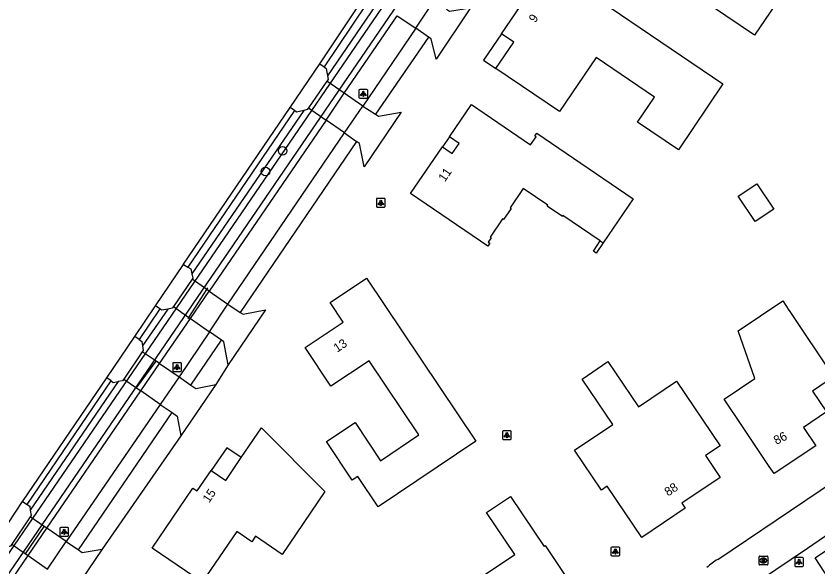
# Model space of a CAD drawing. Extents: x 158797 to 159887, y 384318 to 385255.
# Drawn here: x 158945.2 to 159036.2, y 384830.9 to 384893.5 of the extents above; entities that cross this region are included whole.
import ezdxf

# ---------------------------------------------------------------- set-up
doc = ezdxf.new("R2010")
doc.units = 0
for name, color, linetype in [('IMGEO_Berm_groen', 7, 'Continuous'), ('IMGEO_Boom', 7, 'Continuous'), ('IMGEO_Duiker', 7, 'Continuous'), ('IMGEO_Greppel_droge_sloot', 7, 'Continuous'), ('IMGEO_Groenvoorziening', 7, 'Continuous'), ('IMGEO_Lichtpunt', 7, 'Continuous'), ('IMGEO_Muur', 7, 'Continuous'), ('IMGEO_Pand', 7, 'Continuous'), ('IMGEO_Pand_nummerreeks', 7, 'Continuous'), ('IMGEO_Pand_overbouw', 7, 'Continuous'), ('IMGEO_Rijbaan_lokaal_gesloten', 7, 'Continuous'), ('IMGEO_Rijbaan_lokaal_halfverhard', 7, 'Continuous'), ('IMGEO_Rijbaan_lokaal_open', 7, 'Continuous'), ('IMGEO_Rioolput', 7, 'Continuous'), ('IMGEO_Voetpad_gesloten', 7, 'Continuous'), ('IMGEO_Voetpad_open', 7, 'Continuous')]:
    doc.layers.add(name, color=color, linetype=linetype)

msp = doc.modelspace()

# ---------------------------------------------------------------- linework, layer by layer
at = {"layer": 'IMGEO_Berm_groen'}
for points in [[(158962.43, 384860.223), (158959.562, 384856.029)], [(158956.795, 384851.982), (158946.829, 384837.41)]]:
    msp.add_lwpolyline(points, dxfattribs=at)
at = {"layer": 'IMGEO_Boom'}
for centre in [(158975.46, 384878.168), (158973.5, 384875.847)]:
    msp.add_circle(centre, 0.489, dxfattribs=at)
at = {"layer": 'IMGEO_Duiker'}
for points in [[(158964.726, 384859.119), (158964.826, 384859.275), (158966.867, 384862.445), (158966.983, 384862.625)], [(158958.884, 384851.261), (158961.107, 384854.291)], [(158946.282, 384832.45), (158948.412, 384835.535)]]:
    msp.add_lwpolyline(points, dxfattribs=at)
at = {"layer": 'IMGEO_Greppel_droge_sloot'}
for points in [[(159000.581, 384914.767), (158933.082, 384816.06)], [(158860.704, 384704.496), (158865.586, 384712.552), (158874.82, 384728.136), (158879.769, 384735.7), (158885.859, 384744.611), (158889.814, 384750.397), (158895.665, 384758.96), (158904.883, 384772.441), (158934.173, 384815.304), (158999.419, 384910.783)]]:
    msp.add_lwpolyline(points, dxfattribs=at)
at = {"layer": 'IMGEO_Groenvoorziening'}
for points in [[(158985.982, 384894.666), (158980.534, 384886.698)], [(158982.459, 384884.718), (158988.462, 384893.502)], [(158977.846, 384882.767), (158965.16, 384864.217)], [(158980.382, 384881.678), (158967.118, 384862.269)], [(158961.487, 384854.03), (158964.992, 384859.158)], [(158969.286, 384853.901), (158967.876, 384851.67)], [(158948.709, 384835.331), (158959.366, 384850.926)], [(158963.909, 384845.829), (158954.984, 384832.978)], [(158933.128, 384812.532), (158946.591, 384832.233)]]:
    msp.add_lwpolyline(points, dxfattribs=at)
at = {"layer": 'IMGEO_Lichtpunt'}
for p, q in [((158984.119, 384885.053), (158984.119, 384884.246)), ((158984.119, 384885.053), (158984.119, 384884.246)), ((158985.021, 384885.148), (158984.213, 384885.148)), ((158985.021, 384885.148), (158984.213, 384885.148)), ((158985.115, 384884.246), (158985.115, 384885.053)), ((158985.115, 384884.246), (158985.115, 384885.053)), ((158984.213, 384884.152), (158985.021, 384884.152)), ((158984.213, 384884.152), (158985.021, 384884.152)), ((158986.101, 384872.684), (158986.101, 384871.877)), ((158986.101, 384872.684), (158986.101, 384871.877)), ((158987.003, 384872.779), (158986.195, 384872.779)), ((158987.003, 384872.779), (158986.195, 384872.779)), ((158987.097, 384871.877), (158987.097, 384872.684)), ((158987.097, 384871.877), (158987.097, 384872.684)), ((158986.195, 384871.783), (158987.003, 384871.783)), ((158986.195, 384871.783), (158987.003, 384871.783)), ((158962.982, 384854.039), (158962.982, 384853.232)), ((158962.982, 384854.039), (158962.982, 384853.232)), ((158963.884, 384854.134), (158963.076, 384854.134)), ((158963.884, 384854.134), (158963.076, 384854.134)), ((158963.978, 384853.232), (158963.978, 384854.039)), ((158963.978, 384853.232), (158963.978, 384854.039)), ((158963.076, 384853.138), (158963.884, 384853.138)), ((158963.076, 384853.138), (158963.884, 384853.138)), ((159000.403, 384846.31), (159000.403, 384845.503)), ((159000.403, 384846.31), (159000.403, 384845.503)), ((159001.305, 384846.405), (159000.497, 384846.405)), ((159001.305, 384846.405), (159000.497, 384846.405)), ((159001.399, 384845.503), (159001.399, 384846.31)), ((159001.399, 384845.503), (159001.399, 384846.31)), ((159000.497, 384845.409), (159001.305, 384845.409)), ((159000.497, 384845.409), (159001.305, 384845.409)), ((158950.181, 384835.336), (158950.181, 384834.529)), ((158950.181, 384835.336), (158950.181, 384834.529)), ((158951.083, 384835.431), (158950.275, 384835.431)), ((158951.083, 384835.431), (158950.275, 384835.431)), ((158951.177, 384834.529), (158951.177, 384835.336)), ((158951.177, 384834.529), (158951.177, 384835.336)), ((158950.275, 384834.435), (158951.083, 384834.435)), ((158950.275, 384834.435), (158951.083, 384834.435)), ((159012.717, 384833.106), (159012.717, 384832.299)), ((159012.717, 384833.106), (159012.717, 384832.299)), ((159013.619, 384833.201), (159012.811, 384833.201)), ((159013.619, 384833.201), (159012.811, 384833.201)), ((159013.713, 384832.299), (159013.713, 384833.106)), ((159013.713, 384832.299), (159013.713, 384833.106)), ((159012.811, 384832.205), (159013.619, 384832.205)), ((159012.811, 384832.205), (159013.619, 384832.205)), ((159033.559, 384831.915), (159033.559, 384831.108)), ((159033.559, 384831.915), (159033.559, 384831.108)), ((159034.461, 384832.01), (159033.653, 384832.01)), ((159034.461, 384832.01), (159033.653, 384832.01)), ((159034.555, 384831.108), (159034.555, 384831.915)), ((159034.555, 384831.108), (159034.555, 384831.915)), ((159033.653, 384831.014), (159034.461, 384831.014)), ((159033.653, 384831.014), (159034.461, 384831.014))]:
    msp.add_line(p, q, dxfattribs=at)
for points in [[(158984.493, 384884.717), (158984.532, 384884.689), (158984.344, 384884.427), (158984.306, 384884.454), (158984.493, 384884.717)], [(158984.595, 384884.669), (158984.642, 384884.669), (158984.642, 384884.347), (158984.595, 384884.347), (158984.595, 384884.669)], [(158984.705, 384884.689), (158984.743, 384884.716), (158984.93, 384884.454), (158984.891, 384884.426), (158984.705, 384884.689)], [(158986.475, 384872.348), (158986.514, 384872.32), (158986.326, 384872.058), (158986.288, 384872.085), (158986.475, 384872.348)], [(158986.577, 384872.3), (158986.624, 384872.3), (158986.624, 384871.978), (158986.577, 384871.978), (158986.577, 384872.3)], [(158986.687, 384872.32), (158986.725, 384872.347), (158986.912, 384872.085), (158986.873, 384872.057), (158986.687, 384872.32)], [(158963.356, 384853.703), (158963.395, 384853.675), (158963.207, 384853.413), (158963.169, 384853.44), (158963.356, 384853.703)], [(158963.458, 384853.655), (158963.505, 384853.655), (158963.505, 384853.333), (158963.458, 384853.333), (158963.458, 384853.655)], [(158963.568, 384853.675), (158963.606, 384853.702), (158963.793, 384853.44), (158963.754, 384853.412), (158963.568, 384853.675)], [(159000.777, 384845.974), (159000.816, 384845.946), (159000.628, 384845.684), (159000.59, 384845.711), (159000.777, 384845.974)], [(159000.879, 384845.926), (159000.926, 384845.926), (159000.926, 384845.604), (159000.879, 384845.604), (159000.879, 384845.926)], [(159000.989, 384845.946), (159001.027, 384845.973), (159001.214, 384845.711), (159001.175, 384845.683), (159000.989, 384845.946)], [(158950.555, 384835), (158950.594, 384834.972), (158950.406, 384834.71), (158950.368, 384834.737), (158950.555, 384835)], [(158950.657, 384834.952), (158950.704, 384834.952), (158950.704, 384834.63), (158950.657, 384834.63), (158950.657, 384834.952)], [(158950.767, 384834.972), (158950.805, 384834.999), (158950.992, 384834.737), (158950.953, 384834.709), (158950.767, 384834.972)], [(159013.091, 384832.77), (159013.13, 384832.742), (159012.942, 384832.48), (159012.904, 384832.507), (159013.091, 384832.77)], [(159013.193, 384832.722), (159013.24, 384832.722), (159013.24, 384832.4), (159013.193, 384832.4), (159013.193, 384832.722)], [(159013.303, 384832.742), (159013.341, 384832.769), (159013.528, 384832.507), (159013.489, 384832.479), (159013.303, 384832.742)], [(159033.933, 384831.579), (159033.972, 384831.551), (159033.784, 384831.289), (159033.746, 384831.316), (159033.933, 384831.579)], [(159034.035, 384831.531), (159034.082, 384831.531), (159034.082, 384831.209), (159034.035, 384831.209), (159034.035, 384831.531)], [(159034.145, 384831.551), (159034.183, 384831.578), (159034.37, 384831.316), (159034.331, 384831.288), (159034.145, 384831.551)]]:
    msp.add_lwpolyline(points, dxfattribs=at)
for centre in [(158984.618, 384884.851), (158986.6, 384872.482), (158963.481, 384853.837), (159000.902, 384846.108), (158950.68, 384835.134), (159013.216, 384832.904), (159034.058, 384831.713)]:
    msp.add_circle(centre, 0.0994, dxfattribs=at)
for centre, start, end in [((158984.213, 384885.053), 90, 180), ((158984.213, 384885.053), 90, 180), ((158985.021, 384885.053), 0, 90), ((158985.021, 384885.053), 0, 90), ((158984.213, 384884.246), 180, 270), ((158984.213, 384884.246), 180, 270), ((158985.021, 384884.246), 270, 0), ((158985.021, 384884.246), 270, 360), ((158986.195, 384872.684), 90, 180), ((158986.195, 384872.684), 90, 180), ((158987.003, 384872.684), 0, 90), ((158987.003, 384872.684), 0, 90), ((158986.195, 384871.877), 180, 270), ((158986.195, 384871.877), 180, 270), ((158987.003, 384871.877), 270, 0), ((158987.003, 384871.877), 270, 360), ((158963.076, 384854.039), 90, 180), ((158963.076, 384854.039), 90, 180), ((158963.884, 384854.039), 0, 90), ((158963.884, 384854.039), 0, 90), ((158963.076, 384853.232), 180, 270), ((158963.076, 384853.232), 180, 270), ((158963.884, 384853.232), 270, 0), ((158963.884, 384853.232), 270, 360), ((159000.497, 384846.31), 90, 180), ((159000.497, 384846.31), 90, 180), ((159001.305, 384846.31), 0, 90), ((159001.305, 384846.31), 0, 90), ((159000.497, 384845.503), 180, 270), ((159000.497, 384845.503), 180, 270), ((159001.305, 384845.503), 270, 0), ((159001.305, 384845.503), 270, 360), ((158950.275, 384835.336), 90, 180), ((158950.275, 384835.336), 90, 180), ((158951.083, 384835.336), 0, 90), ((158951.083, 384835.336), 0, 90), ((158950.275, 384834.529), 180, 270), ((158950.275, 384834.529), 180, 270), ((158951.083, 384834.529), 270, 0), ((158951.083, 384834.529), 270, 360), ((159012.811, 384833.106), 90, 180), ((159012.811, 384833.106), 90, 180), ((159013.619, 384833.106), 0, 90), ((159013.619, 384833.106), 0, 90), ((159012.811, 384832.299), 180, 270), ((159012.811, 384832.299), 180, 270), ((159013.619, 384832.299), 270, 0), ((159013.619, 384832.299), 270, 360), ((159033.653, 384831.915), 90, 180), ((159033.653, 384831.915), 90, 180), ((159034.461, 384831.915), 0, 90), ((159034.461, 384831.915), 0, 90), ((159033.653, 384831.108), 180, 270), ((159033.653, 384831.108), 180, 270), ((159034.461, 384831.108), 270, 0), ((159034.461, 384831.108), 270, 360)]:
    msp.add_arc(centre, 0.0946, start, end, dxfattribs=at)
at = {"layer": 'IMGEO_Muur'}
msp.add_lwpolyline([(159011.829, 384867.738), (159011.04, 384866.573), (159010.716, 384866.797), (159011.506, 384867.958)], dxfattribs=at)
at = {"layer": 'IMGEO_Pand'}
for points in [[(159015.875, 384900.192), (159018.834, 384904.498), (159019.364, 384905.269), (159019.421, 384905.352), (159021.623, 384908.555), (159021.682, 384908.641), (159021.694, 384908.658), (159034.76, 384899.792), (159028.998, 384891.291), (159015.875, 384900.192)], [(159011.04, 384888.774), (159006.868, 384882.635), (158999.666, 384887.522), (159001.7, 384890.513), (159000.294, 384891.469), (159005.589, 384899.258), (159025.424, 384885.771), (159020.365, 384878.305), (159015.728, 384881.447), (159017.653, 384884.287), (159011.04, 384888.774)], [(159011.506, 384867.958), (159007.264, 384870.84), (159007.196, 384870.739), (159005.478, 384871.913), (159005.546, 384872.012), (159002.764, 384873.909), (159001.27, 384871.702), (159001.372, 384871.631), (159000.518, 384870.374), (159000.414, 384870.445), (158999.02, 384868.387), (158999.119, 384868.319), (158998.781, 384867.822), (158998.962, 384867.697), (158998.741, 384867.376), (158989.978, 384873.324), (158993.603, 384878.635), (158994.71, 384877.879), (158995.481, 384879.008), (158994.374, 384879.764), (158996.871, 384883.423), (159003.602, 384878.851), (159004.228, 384879.771), (159004.079, 384879.872), (159004.298, 384880.195), (159015.218, 384872.74), (159011.829, 384867.738)], [(159027.164, 384873.025), (159029.262, 384874.429), (159031.177, 384871.568), (159029.08, 384870.164), (159027.164, 384873.025)], [(159011.506, 384867.958), (159011.829, 384867.738)], [(158986.293, 384837.782), (158983.977, 384841.225), (158983.342, 384840.798), (158980.426, 384845.178), (158983.673, 384847.339), (158986.553, 384843.009), (158990.899, 384845.935), (158985.261, 384854.357), (158980.931, 384851.468), (158978.016, 384855.838), (158982.332, 384858.725), (158980.863, 384860.973), (158984.967, 384863.713), (158997.375, 384845.232), (158986.293, 384837.782)], [(159025.553, 384850), (159029.032, 384852.333), (159027.162, 384857.757), (159032.196, 384861.138), (159032.903, 384860.082), (159032.92, 384860.056), (159037.982, 384852.519), (159035.574, 384850.902), (159037.16, 384848.541), (159034.555, 384846.792), (159035.95, 384844.712), (159031.225, 384841.543), (159030.677, 384842.359), (159027.494, 384847.106), (159025.553, 384850)], [(159012.274, 384840.105), (159011.634, 384839.672), (159008.574, 384844.194), (159012.914, 384847.131), (159009.429, 384852.279), (159012.353, 384854.258), (159015.834, 384849.113), (159020.163, 384852.043), (159025.111, 384844.69), (159023.449, 384843.588), (159025.118, 384841.102), (159020.761, 384838.175), (159021.123, 384837.636), (159016.198, 384834.308), (159012.274, 384840.105)], [(158975.414, 384832.374), (158972.397, 384834.428), (158971.973, 384833.806), (158970.251, 384834.978), (158966.332, 384829.22), (158960.645, 384833.09), (158965.284, 384839.907), (158965.772, 384839.575), (158967.348, 384841.89), (158968.995, 384840.769), (158970.764, 384843.357), (158973.066, 384846.723), (158980.262, 384839.497), (158975.414, 384832.374)], [(158998.352, 384830.067), (159001.8, 384832.363), (158998.598, 384837.128), (159001.316, 384838.955), (159005.13, 384833.279), (159005.266, 384833.371), (159007.67, 384829.769), (159007.516, 384829.666), (159013.04, 384821.413), (159013.085, 384821.346), (159010.36, 384819.522), (159010.989, 384818.583), (159010.876, 384818.508), (159011.37, 384817.771), (159006.845, 384814.748), (159005.112, 384817.324), (159005.278, 384817.436), (159003.088, 384820.674), (159004.176, 384821.398), (158998.352, 384830.067)]]:
    msp.add_lwpolyline(points, dxfattribs=at)
at = {"layer": 'IMGEO_Pand_overbouw'}
for points in [[(159000.294, 384891.469), (158998.26, 384888.476), (158999.666, 384887.522), (159001.7, 384890.513)], [(158994.374, 384879.764), (158993.603, 384878.635), (158994.71, 384877.879), (158995.481, 384879.008)], [(158967.348, 384841.89), (158968.995, 384840.769), (158970.764, 384843.357), (158969.112, 384844.481)]]:
    msp.add_lwpolyline(points, close=True, dxfattribs=at)
at = {"layer": 'IMGEO_Rijbaan_lokaal_gesloten'}
for points in [[(158979.681, 384888.06), (158979.682, 384888.062), (158984.463, 384895.206)], [(158990.581, 384892.084), (158992.62, 384895.18)], [(158988.462, 384893.502), (158990.581, 384892.084)], [(158976.299, 384883.094), (158979.681, 384888.06)], [(158978.393, 384883.063), (158980.382, 384881.678), (158982.459, 384884.718), (158980.472, 384886.086), (158978.393, 384883.063)], [(158980.382, 384881.678), (158982.459, 384884.718)], [(158984.577, 384883.259), (158982.459, 384884.718)], [(158964.203, 384865.296), (158964.218, 384865.318), (158976.299, 384883.094)], [(158982.48, 384880.216), (158984.577, 384883.259)], [(158982.48, 384880.216), (158980.382, 384881.678)], [(158961.017, 384860.587), (158964.203, 384865.296)], [(158967.118, 384862.269), (158966.867, 384862.445), (158965.192, 384863.623), (158963.065, 384860.518), (158964.826, 384859.275), (158964.992, 384859.158), (158967.118, 384862.269)], [(158964.992, 384859.158), (158967.118, 384862.269)], [(158967.118, 384862.269), (158969.244, 384860.774)], [(158967.161, 384857.628), (158969.244, 384860.774)], [(158958.685, 384857.123), (158961.017, 384860.587)], [(158964.992, 384859.158), (158967.161, 384857.628)], [(158955.504, 384852.399), (158958.685, 384857.123)], [(158961.487, 384854.03), (158961.107, 384854.291), (158959.531, 384855.374), (158957.432, 384852.267), (158958.884, 384851.261), (158959.366, 384850.926), (158961.487, 384854.03)], [(158959.366, 384850.926), (158961.487, 384854.03)], [(158961.487, 384854.03), (158963.7, 384852.509)], [(158945.952, 384838.368), (158945.978, 384838.407), (158955.504, 384852.399)], [(158963.7, 384852.509), (158961.565, 384849.402)], [(158961.565, 384849.402), (158959.366, 384850.926)], [(158942.743, 384833.54), (158945.952, 384838.368)], [(158948.709, 384835.331), (158948.412, 384835.535), (158946.824, 384836.625), (158944.729, 384833.54), (158946.282, 384832.45), (158946.591, 384832.233), (158948.709, 384835.331)], [(158946.591, 384832.233), (158948.709, 384835.331)], [(158950.913, 384833.82), (158948.709, 384835.331)], [(158948.777, 384830.698), (158950.913, 384833.82)], [(158946.591, 384832.233), (158948.777, 384830.698)]]:
    msp.add_lwpolyline(points, dxfattribs=at)
at = {"layer": 'IMGEO_Rijbaan_lokaal_halfverhard'}
for points in [[(158984.962, 384894.872), (158980.163, 384887.702)], [(158976.794, 384882.755), (158964.719, 384864.988)], [(158961.519, 384860.258), (158959.171, 384856.771)], [(158946.453, 384838.038), (158955.997, 384852.057)]]:
    msp.add_lwpolyline(points, dxfattribs=at)
at = {"layer": 'IMGEO_Rijbaan_lokaal_open'}
for points in [[(158994.05, 384894.26), (158994.408, 384894.022), (158996.766, 384894.403), (158992.864, 384888.603), (158992.309, 384890.885), (158991.997, 384891.099)], [(158991.997, 384891.099), (158990.581, 384892.084)], [(158979.681, 384888.06), (158980.163, 384887.702)], [(158980.163, 384887.702), (158980.381, 384887.539), (158980.534, 384886.698)], [(158980.534, 384886.698), (158980.609, 384886.285), (158980.472, 384886.086), (158978.393, 384883.063), (158978.255, 384882.862), (158977.846, 384882.767)], [(159024.825, 384831.804), (159044.696, 384845.173), (159051.975, 384850.093), (159072.358, 384863.736), (159083.984, 384871.536), (159097.187, 384880.393), (159102.738, 384884.143)], [(158976.794, 384882.755), (158976.299, 384883.094)], [(158977.846, 384882.767), (158977.047, 384882.582), (158976.794, 384882.755)], [(158984.577, 384883.259), (158985.995, 384882.343)], [(158985.995, 384882.343), (158986.33, 384882.096), (158988.909, 384882.554), (158984.706, 384876.348), (158984.199, 384879.013), (158983.842, 384879.238)], [(158982.48, 384880.216), (158983.842, 384879.238)], [(158964.203, 384865.296), (158964.719, 384864.988)], [(158964.719, 384864.988), (158965.045, 384864.795), (158965.16, 384864.217)], [(158965.16, 384864.217), (158965.259, 384863.721), (158965.192, 384863.623), (158963.065, 384860.518), (158962.929, 384860.319), (158962.43, 384860.223)], [(158969.244, 384860.774), (158970.644, 384859.843)], [(158961.519, 384860.258), (158961.017, 384860.587)], [(158962.43, 384860.223), (158961.765, 384860.096), (158961.519, 384860.258)], [(158970.644, 384859.843), (158970.967, 384859.628), (158973.515, 384860.15), (158969.286, 384853.901)], [(158959.171, 384856.771), (158958.685, 384857.123)], [(158968.523, 384856.7), (158967.161, 384857.628)], [(158959.171, 384856.771), (158959.485, 384856.543), (158959.562, 384856.029)], [(158969.286, 384853.901), (158968.796, 384856.514), (158968.523, 384856.7)], [(158959.562, 384856.029), (158959.636, 384855.529), (158959.531, 384855.374), (158957.432, 384852.267), (158957.293, 384852.062), (158956.795, 384851.982)], [(158955.997, 384852.057), (158955.504, 384852.399)], [(158955.997, 384852.057), (158956.234, 384851.893), (158956.795, 384851.982)], [(158963.7, 384852.509), (158965.049, 384851.598)], [(158967.876, 384851.67), (158963.909, 384845.829)], [(158965.049, 384851.598), (158965.607, 384851.221), (158967.876, 384851.67)], [(159062.256, 384851.349), (159060.561, 384850.194), (159051.296, 384843.964), (159040.9, 384837.091), (159035.001, 384833.037), (159029.568, 384829.373)], [(158961.565, 384849.402), (158962.916, 384848.47)], [(158962.916, 384848.47), (158963.483, 384848.079), (158963.909, 384845.829)], [(158945.952, 384838.368), (158946.453, 384838.038)], [(158946.453, 384838.038), (158946.762, 384837.834), (158946.829, 384837.41)], [(158946.829, 384837.41), (158946.929, 384836.78), (158946.824, 384836.625), (158944.729, 384833.54), (158944.566, 384833.3), (158943.884, 384833.103)], [(158950.913, 384833.82), (158952.303, 384832.882)], [(158954.984, 384832.978), (158951.086, 384827.221)], [(158952.303, 384832.882), (158952.713, 384832.605), (158954.984, 384832.978)]]:
    msp.add_lwpolyline(points, dxfattribs=at)
msp.add_arc((159028.234, 384826.022), 6.712, 120.51798, 133.65463, dxfattribs=at)
at = {"layer": 'IMGEO_Rioolput'}
for p, q in [((159029.511, 384831.252), (159029.511, 384832.104)), ((159029.586, 384832.178), (159030.438, 384832.178)), ((159029.999, 384831.958), (159030.024, 384831.958)), ((159030.512, 384832.104), (159030.512, 384831.252)), ((159030.438, 384831.178), (159029.586, 384831.178)), ((159030.022, 384831.398), (159029.997, 384831.398))]:
    msp.add_line(p, q, dxfattribs=at)
for points in [[(159029.511, 384831.252), (159029.511, 384832.104)], [(159029.586, 384832.178), (159030.438, 384832.178)], [(159030.1, 384831.876), (159029.848, 384831.878), (159029.848, 384831.478)], [(159029.848, 384831.478), (159029.972, 384831.478), (159029.972, 384831.64), (159029.983, 384831.64)], [(159030.026, 384831.797), (159029.972, 384831.797), (159029.972, 384831.716)], [(159029.972, 384831.716), (159030.024, 384831.716)], [(159030.03, 384831.611), (159030.101, 384831.478), (159030.241, 384831.478), (159030.176, 384831.604)], [(159030.512, 384832.104), (159030.512, 384831.252)], [(159030.438, 384831.178), (159029.586, 384831.178)]]:
    msp.add_lwpolyline(points, dxfattribs=at)
for centre, radius, start, end in [((159029.588, 384832.102), 0.0765, 91.55205, 178.44795), ((159029.588, 384832.102), 0.0765, 91.55205, 178.44795), ((159029.982, 384831.587), 0.0533, 26.02933, 88.69889), ((159030.008, 384831.905), 0.19, 274.7715, 282.96867), ((159030.032, 384831.701), 0.0964, 77.00612, 93.18647), ((159030.046, 384831.758), 0.0378, 276.66336, 79.67722), ((159030.099, 384831.766), 0.109, 350.36119, 89.41601), ((159030.097, 384831.766), 0.112, 277.58423, 350.98172), ((159030.081, 384831.551), 0.108, 29.51342, 73.79051), ((159030.436, 384832.102), 0.0765, 1.55205, 88.44795), ((159030.436, 384832.102), 0.0765, 1.55205, 88.44795), ((159029.588, 384831.254), 0.0765, 181.55205, 268.44795), ((159029.588, 384831.254), 0.0765, 181.55205, 268.44795), ((159030.436, 384831.254), 0.0765, 271.55205, 358.44795), ((159030.436, 384831.254), 0.0765, 271.55205, 358.44795)]:
    msp.add_arc(centre, radius, start, end, dxfattribs=at)
for centre, major_axis, ratio, start_param, end_param in [((159029.998, 384831.678), (-0.387, 0.002), 0.722429, 4.712389, 7.853982), ((159030.023, 384831.678), (-0.39, 0.002), 0.717154, 1.570796, 4.712389)]:
    msp.add_ellipse(centre, major_axis=major_axis, ratio=ratio, start_param=start_param, end_param=end_param, dxfattribs=at)
at = {"layer": 'IMGEO_Voetpad_gesloten'}
for points in [[(158990.581, 384892.084), (158984.577, 384883.259)], [(158991.997, 384891.099), (158985.995, 384882.343)], [(158969.244, 384860.774), (158982.48, 384880.216)], [(158983.842, 384879.238), (158970.644, 384859.843)], [(158967.161, 384857.628), (158963.7, 384852.509)], [(158965.049, 384851.598), (158968.523, 384856.7)], [(158961.565, 384849.402), (158950.913, 384833.82)], [(158952.303, 384832.882), (158962.916, 384848.47)]]:
    msp.add_lwpolyline(points, dxfattribs=at)
at = {"layer": 'IMGEO_Voetpad_open'}
msp.add_lwpolyline([(159031.911, 384823.899), (159031.99, 384823.78), (159038.428, 384828.093), (159035.883, 384831.966), (159053.058, 384843.462), (159063.047, 384850.2), (159062.256, 384851.349)], dxfattribs=at)

# ---------------------------------------------------------------- texts
at = {"layer": 'IMGEO_Pand_nummerreeks'}
for s, rotation, p in [('9', 55.79463, (159004.122, 384892.653)), ('11', 55.68577, (158993.866, 384874.586)), ('13', 33.78159, (158981.646, 384855.259)), ('86', 26.86026, (159031.482, 384844.796)), ('15', 55.76598, (158967.111, 384838.147)), ('88', 33.89045, (159019.195, 384838.93))]:
    msp.add_text(s, height=1, rotation=rotation, dxfattribs=at).set_placement(p)

doc.saveas('drawing.dxf')
